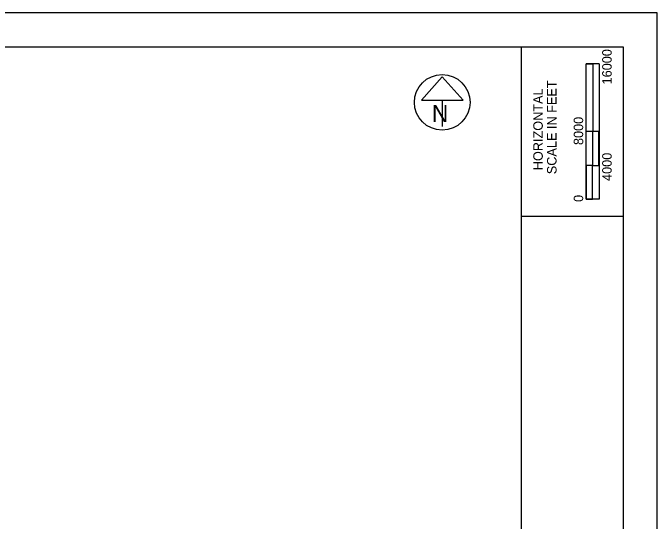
# Model space of a CAD drawing. Extents: x 2004415 to 2276415, y 751181 to 927181.
# Drawn here: x 2200451 to 2276415, y 867212 to 927181 of the extents above; entities that cross this region are included whole.
import ezdxf

# ---------------------------------------------------------------- set-up
doc = ezdxf.new("R2010")
doc.units = 0
for name, color, linetype in [('SH_Border', 7, 'Continuous'), ('SH_Cut_Line', 7, 'Continuous'), ('SH_Data', 7, 'Continuous'), ('SH_Masking', 7, 'Continuous'), ('SH_Text', 7, 'Continuous')]:
    doc.layers.add(name, color=color, linetype=linetype)

msp = doc.modelspace()

# ---------------------------------------------------------------- linework, layer by layer
at = {"layer": 'SH_Border'}
for p, q in [((2260415, 755181), (2260415, 923181)), ((2260415, 903181), (2272415, 903181))]:
    msp.add_line(p, q, dxfattribs=at)
msp.add_lwpolyline([(2016415, 923181), (2272415, 923181), (2272415, 755181), (2016415, 755181)], close=True, dxfattribs=at)
at = {"layer": 'SH_Cut_Line'}
msp.add_lwpolyline([(2004415, 751181), (2276415, 751181), (2276415, 927181), (2004415, 927181)], close=True, dxfattribs=at)
at = {"layer": 'SH_Data'}
for p, q in [((2268069, 905181), (2268069, 921181)), ((2269569, 921181), (2268069, 921181)), ((2268069, 913181), (2268069, 921181)), ((2268069, 921181), (2268815, 921181)), ((2268815, 921181), (2268822, 921181)), ((2268822, 921181), (2268822, 913181)), ((2269569, 921181), (2269569, 905181)), ((2268822, 913181), (2268069, 913181)), ((2269562, 913181), (2268815, 913181)), ((2268815, 913181), (2268815, 909181)), ((2269562, 909181), (2269562, 913181)), ((2268815, 909181), (2268069, 909181)), ((2268069, 909181), (2268069, 905181)), ((2268815, 905181), (2268815, 909181)), ((2268815, 909181), (2269562, 909181)), ((2269569, 905181), (2268069, 905181)), ((2268069, 905181), (2268815, 905181))]:
    msp.add_line(p, q, dxfattribs=at)
at = {"layer": 'SH_Masking'}
msp.add_circle((2251076, 916625), 3280, dxfattribs=at)
at = {"layer": 'SH_Text'}
for p, q in [((2251076, 919615), (2248616, 916885)), ((2253537, 916885), (2251076, 919615)), ((2248616, 916885), (2253537, 916885)), ((2251076, 916885), (2251076, 913791))]:
    msp.add_line(p, q, dxfattribs=at)
msp.add_circle((2251076, 916625), 3280, dxfattribs=at)

# ---------------------------------------------------------------- texts
at = {"layer": 'SH_Data'}
for s, p in [('16000', (2271058, 918739)), ('SCALE IN FEET', (2264555, 908145)), ('HORIZONTAL', (2262935, 908614)), ('8000', (2267699, 911586)), ('4000', (2271058, 907348)), ('0', (2267699, 904871))]:
    msp.add_text(s, height=1120, rotation=90, dxfattribs=at).set_placement(p)
at = {"layer": 'SH_Text'}
msp.add_text('N', height=2000, dxfattribs=at).set_placement((2249866, 914294))

doc.saveas('drawing.dxf')
